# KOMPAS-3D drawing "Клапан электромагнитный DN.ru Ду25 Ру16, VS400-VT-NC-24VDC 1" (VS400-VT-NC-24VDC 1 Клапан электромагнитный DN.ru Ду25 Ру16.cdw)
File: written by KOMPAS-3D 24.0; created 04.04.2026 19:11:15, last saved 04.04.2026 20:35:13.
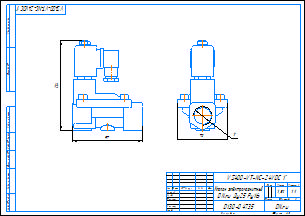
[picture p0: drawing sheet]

Document properties: c3d_UniqueCompID: ef56311e-7521-43dc-8291-0e6108b3d81d; Обозначение: VS400-ET-NC-220VAC 1; Наименование: Клапан электромагнитный DN.ru Ду25 Ру16; Автор: artio; Класс точности: c; Знак неуказанной шероховатости: Шероховатость не задана; Рассекать на разрезах: Да; c3d_UniqueCompID: ef56311e-7521-43dc-8291-0e6108b3d81d; Обозначение: VS400-ET-NC-220VAC 1-2; Наименование: Клапан электромагнитный DN.ru Ду15 Ру16; Автор: artio; Класс точности: c; Знак неуказанной шероховатости: Шероховатость не задана; Рассекать на разрезах: Да; c3d_UniqueCompID: ef56311e-7521-43dc-8291-0e6108b3d81d; Обозначение: VS400-ET-NC-220VAC 3-4; Наименование: Клапан электромагнитный DN.ru Ду20 Ру16; Автор: artio; Класс точности: c; Знак неуказанной шероховатости: Шероховатость не задана; Рассекать на разрезах: Да; c3d_UniqueCompID: ef56311e-7521-43dc-8291-0e6108b3d81d; Обозначение: VS400-ET-NC-220VAC 3-8; Наименование: Клапан электромагнитный DN.ru Ду10 Ру16; Автор: artio; Класс точности: c; Знак неуказанной шероховатости: Шероховатость не задана; Рассекать на разрезах: Да; Автор: artio; Форматы листов документа: A3; Полное имя файла: VS400-VT-NC-24VDC 1 Клапан электромагнитный DN.ru Ду25 Ру16.m3d; Масса: 1.524; Наименование: Клапан электромагнитный DN.ru Ду25 Ру16; Количество листов документа: 1; Примечание: D130-04735

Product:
- Body: Тело 1  | qty 1
    Масса: 1.76797
- Part/product: Клапан электромагнитный DN.ru Ду25 Ру16  | designation VS400-VT-NC-24VDC 1
    Масса: 1.524
    Раздел спецификации: Прочие изделия
    Примечание: D130-04735
    additional columns: ef56311e-7521-43dc-8291-0e6108b3d81d; VS400-ET-NC-220VAC 1; artio; c; Шероховатость не задана; Да

Views: Вид 1, Спереди
Referenced files in C:\Users\artio\OneDrive\Рабочий стол\Клапан электромагнитный DN.ru\VS400-ET-NC\VS400-ET-NC-24VDC\: VS400-ET-NC-24VDC 3-8 Клапан электромагнитный DN.ru Ду10 Ру16.m3d
Referenced files in C:\Users\artio\OneDrive\Рабочий стол\Клапан электромагнитный DN.ru\VS400-VT-NC\VS400-VT-NC-24VDC\: VS400-VT-NC-24VDC 1 Клапан электромагнитный DN.ru Ду25 Ру16.m3d
Referenced files in C:\Users\artio\OneDrive\Рабочий стол\Клапан электромагнитный DN.ru\VS400-ET-NC\: VS400-ET-NC-24VDC 3-8 Клапан электромагнитный DN.ru Ду10 Ру16.cdw
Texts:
  VS400-VT-NC-24VDC 1
  Клапан электромагнитный
  DN.ru Ду25 Ру16
  VS400-VT-NC-24VDC 1"
  VS400-VT-NC-24VDC 1"-
  Клапан электромагнитный DN.ru Ду25 Ру16
  VS400-VT-NC-24VDC 1 Клапан электромагнитный DN.ru Ду25 Ру16
Dimensions and other numbers on the sheet: 0; 3; 2; 4; 70; 1:1; 1; 1,52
